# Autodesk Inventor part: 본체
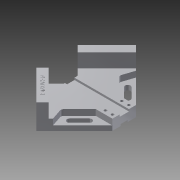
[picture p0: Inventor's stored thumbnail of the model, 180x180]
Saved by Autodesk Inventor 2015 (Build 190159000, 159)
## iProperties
Created: 2019-04
Part Number: 본체
Material: 알루미늄 6061
Document SubType Name: Modeling
Designer: LINEART-SSD.D4.16.04
Density: 2.7 g/cm^3
Appearance: 알루미늄 - 평지
Mass: 608.093 g
Surface Area: 428.235 cm^2
Volume: 225.22 cm^3
Author: LINEART-SSD.D4.16.04
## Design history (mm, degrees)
sketch "스케치1"
  geometry: L1 (-84.853, 0)-(0, -84.853); L2 (0, -84.853)-(84.853, 0); L3 (84.853, 0)-(0, 84.853); L4 (0, 84.853)-(-84.853, 0); L5 (-84.853, 0)-(84.853, 0); L6 (0, -84.853)-(0, 84.853); L7 (-84.853, 0)-(35.147, 0); 1 further point
  constraints: 14 end point, 2 midpoint, 2 parallel, 1 equal length, 1 horizontal, 1 perpendicular
  dimensions: "d0" = 120 distance of L1.start L1.end; "d1" = 45 deg angle of L1 L7; "d2" = 120 distance of L2.end L1.end
extrude "돌출1" new body sketch "스케치1" distance "d3" = 42; taper "d4" = 0 deg
sketch "스케치2"
  geometry: L1 (-84.853, 0)-(0, 84.853); L2 (84.853, 0)-(0, 84.853) reference; L3 (-74.246, -10.607)-(0, 63.64); L4 (0, 63.64)-(74.246, -10.607); L5 (-74.246, -10.607)-(0, -84.853); L6 (-84.853, 0)-(0, -84.853) reference; L7 (0, -84.853)-(74.246, -10.607); 1 further point
  constraints: 10 end point, 3 perpendicular, 1 collinear, 1 other
  dimensions: "d5" = 15 distance between parallel lines of L1 L3
extrude "돌출2" cut sketch "스케치2" distance "d6" = 24; taper "d7" = 0 deg
sketch "스케치3"
  geometry: L1 (0, 84.853)-(-35.355, 49.497); L2 (0, 84.853)-(-84.853, 0) reference; L3 (0, 84.853)-(35.355, 49.497); L4 (84.853, 0)-(0, 84.853) reference; L5 (35.355, 49.497)-(15.47, 29.612); L6 (-11.322, 29.612)-(-33.281, 51.571); L7 (0, -84.853)-(14, -84.853); L8 (0, -64.853)-(14, -64.853); L9 (4.143, 28.147)-(11.934, 28.147); L10 (4.143, 28.147)-(-7.786, 28.147); A1 r 5 centre (-7.786, 33.147) between (-11.322, 29.612) and (-7.786, 28.147); A2 r 5 centre (11.934, 33.147) between (11.934, 28.147) and (15.47, 29.612); 4 further points
  constraints: 16 end point, 9 point on line, 4 point on circle, 4 tangent, 2 centre point, 2 horizontal, 2 parallel, 1 equal radius, 1 perpendicular
  dimensions: "d8" = 50 distance of L1.start L1.end; "d9" = 50 distance of L1.start L3.end; "d12" = 14 distance of L7.start L7.end; "d13" = 20 distance between parallel lines of L7 L8; "d14" = 93 distance between parallel lines of L8 L9; "d16" = 33.12691 distance of point (-9.857, 28.147) L6.end; "d17" = 30.19387 distance of L3.end point (14.005, 28.147); "d18" = 14 distance of L9.start point (-9.857, 28.147); "d19" = 9.85711 distance of L9.start point (14, 28.147); "d20" = 5 radius of A1; "d97" = 14 distance of L8.start L8.end; "d98" = 20 distance of L7.end L8.end
extrude "돌출3" cut sketch "스케치3" stored distance "d21" = 0; taper "d22" = 0 deg
sketch "스케치4"
  geometry: L1 (0, -84.853)-(25, -84.853); L2 (-11, -64.853)-(25, -64.853); L3 (-11, -64.853)-(-25, -64.853); L4 (25, -64.853)-(25, -84.853); L5 (0, -84.853)-(-25, -84.853); L6 (-25, -84.853)-(-25, -64.853); 1 further point
  constraints: 12 end point, 3 horizontal, 1 parallel, 1 perpendicular, 1 vertical
  dimensions: "d23" = 25 distance of L1.start L1.end; "d24" = 20 distance between parallel lines of L1 L2; "d25" = 14 distance of L2.start L3.end; "d28" = 25 distance of L1.start L5.end
extrude "돌출4" cut sketch "스케치4" stored distance "d29" = 24; taper "d30" = 0 deg
sketch "스케치6"
  geometry: L1 (-7.786, 28.147)-(8.214, 28.147); L2 (11.934, 28.147)-(-7.786, 28.147) reference; L3 (-7.786, 28.147)-(-7.786, -64.853); L4 (8.214, 28.147)-(8.214, -64.853); L5 (-7.786, -64.853)-(8.214, -64.853); L6 (-20, -64.853)-(20, -64.853) reference; 1 further point
  constraints: 8 end point, 1 collinear, 1 point on line, 1 vertical
  dimensions: "d39" = 16 distance of L1.start L1.end; "d95" = 93 distance of L4.end L1.end; "d96" = 16 distance of L4.end L3.end
extrude "돌출5" cut sketch "스케치6" distance "d43" = 3.5; taper "d44" = 0 deg
sketch "스케치7"
  geometry: L1 (8.214, 64.853)-(-7.786, 64.853) reference; L2 (-6, -28.147)-(-6, 64.853); L3 (-6, 64.853)-(6, 64.853); L4 (6, 64.853)-(6, -28.147); L5 (6, -28.147)-(-7.343, -28.147); L6 (-7.786, -28.147)-(11.934, -28.147) reference; 2 further points
  constraints: 8 end point, 4 point on line, 1 parallel
  dimensions: "d47" = 12 distance of L2.end L3.end; "d48" = 93 distance of L2.start L2.end; "d49" = 93 distance of L3.end L4.end; "d50" = 13.34265 distance of L4.end L5.end; "d51" = 6 distance from line of L4 point (0, 0)
extrude "돌출6" cut sketch "스케치7" distance "d52" = 3; taper "d53" = 0 deg
sketch "스케치8"
  geometry: L1 (-84.853, 0)-(-70.711, -14.142); L2 (-84.853, 0)-(-20, -64.853) reference; L3 (-20, -64.853)-(-20, -36.569); L4 (-47.312, -9.256)-(-20, -36.569) reference; L5 (-70.711, -14.142)-(-20, -64.853); L6 (-84.853, 0)-(-77.782, 7.071); L7 (-33.281, 51.571)-(-84.853, 0) reference; L8 (-77.782, 7.071)-(-49.497, -21.213); L9 (-77.782, 7.071)-(-37.782, 7.071); L10 (-49.497, -21.213)-(-32.527, -38.184); L11 (-6, -64.853)-(6, -64.853) reference; L12 (0, -64.853)-(0, 0); L13 (20, -64.853)-(20, -36.569); L14 (70.711, -14.142)-(20, -64.853); L15 (-84.853, 0)-(-63.64, -21.213); L16 (-70.711, -14.142)-(-52.429, -8.048); L17 (70.711, -14.142)-(52.429, -8.048); L18 (20, -36.569)-(47.312, -9.256); A1 r 5 centre (-50.848, -12.792) between (-47.312, -9.256) and (-52.429, -8.048); A2 r 5 centre (50.848, -12.792) between (52.429, -8.048) and (47.312, -9.256); 3 further points
  constraints: 32 end point, 8 symmetric about line, 4 point on circle, 3 point on line, 2 centre point, 2 midpoint, 2 tangent, 2 vertical, 1 collinear, 1 equal length, 1 horizontal, 1 parallel, 2 other
  dimensions: "d54" = 20 distance of L1.start L1.end; "d57" = 10 distance of L1.start L6.end; "d58" = 40 distance of L6.end L8.end; "d59" = 45 deg angle of L8 L9; "d60" = 24 distance of L8.end L10.end; "d64" = 30 distance of L1.start L15.end; "d65" = 5 radius of A1; "d66" = 19.27051 distance of L1.end L16.end
extrude "돌출7" cut sketch "스케치8" distance "d62" = 10; taper "d63" = 0 deg
sketch "스케치10"
  geometry: L1 (-84.853, 0)-(-77.782, 7.071); L2 (-33.281, 51.571)-(-84.853, 0) reference; L3 (-84.853, 0)-(-74.853, 0); L4 (-77.782, 7.071)-(-49.497, -21.213); L5 (-77.782, 7.071)-(-37.782, 7.071); L6 (-49.497, -21.213)-(-32.527, -38.184); L7 (-52.679, -24.395)-(-35.709, -41.366); L8 (-29.345, -35.002)-(-46.315, -18.031); L9 (8.214, -64.853)-(-7.786, -64.853) reference; L10 (0.214, -64.853)-(0.214, 28.391); L11 (29.773, -35.002)-(46.743, -18.031); L12 (53.107, -24.395)-(36.137, -41.366); L13 (49.925, -21.213)-(32.955, -38.184); A1 r 4.5 centre (-49.497, -21.213) between (-46.315, -18.031) and (-52.679, -24.395); A2 r 4.5 centre (-32.527, -38.184) between (-35.709, -41.366) and (-29.345, -35.002); A3 r 4.5 centre (49.925, -21.213) between (53.107, -24.395) and (46.743, -18.031); A4 r 4.5 centre (32.955, -38.184) between (29.773, -35.002) and (36.137, -41.366); 3 further points
  constraints: 26 end point, 8 point on circle, 6 symmetric about line, 4 centre point, 4 tangent, 2 equal length, 2 horizontal, 2 midpoint, 1 collinear, 1 parallel, 1 vertical, 2 other
  dimensions: "d67" = 10 distance of L1.start L1.end; "d68" = 45 deg angle of L3 L1 (derived); "d69" = 40 distance of L1.end L4.end; "d70" = 45 deg angle of L4 L5; "d71" = 24 distance of L4.end L6.end; "d72" = 9 diameter of A2; "d73" = 16.97056 horizontal distance of L13.start L13.end
extrude "돌출8" cut sketch "스케치10" stored distance "d74" = 10; taper "d75" = 0 deg
sketch "스케치11"
  geometry: L1 (8.214, -64.853)-(-7.786, -64.853) reference; L2 (0.214, -64.853)-(14.214, -64.853); L3 (20, -64.853)-(6, -64.853) reference; L4 (14.214, -64.853)-(14.214, -58.853); L5 (14.214, -58.853)-(14.214, -46.853); L6 (8, 28.147)-(8, -64.853) reference; L7 (0.214, -64.853)-(0.214, -27.265); C1 r 2.25 at (14.214, -58.853); C2 r 2.25 at (14.214, -46.853); C3 r 2.25 at (-13.786, -46.853); C4 r 2.25 at (-13.786, -58.853); 1 further point
  constraints: 8 end point, 4 centre point, 2 coincident, 2 point on line, 2 symmetric about line, 1 midpoint, 1 perpendicular, 1 vertical, 2 other
  dimensions: "d76" = 14 distance of L2.start L2.end; "d77" = 6 distance of L2.end L4.end; "d78" = 12 distance of L4.end L5.end; "d79" = 4.5 diameter of C1; "d80" = 4.5 diameter of C2; "d84" = 37.58774 distance of L2.start L7.end
extrude "돌출9" cut sketch "스케치11" distance "d82" = 10; taper "d83" = 0 deg
sketch "스케치13"
  geometry: C1 r 2.25 at (0, 0) reference; C2 r 4 at (0, 0); C3 r 2.25 at (0, -12) reference; C4 r 4 at (0, -12); C5 r 2.25 at (28, 0) reference; C6 r 4 at (28, 0); C7 r 2.25 at (28, -12) reference; C8 r 4 at (28, -12); 1 further point
  constraints: 4 centre point, 4 coincident
  dimensions: "d85" = 8 diameter of C2; "d86" = 8 diameter of C4; "d87" = 8 diameter of C6; "d88" = 8 diameter of C8
extrude "돌출10" cut sketch "스케치13" stored distance "d89" = 10; taper "d90" = 0 deg
sketch "스케치14"
  geometry: L1 (-33.281, 51.571)-(-84.853, 0) reference; L2 (-59.067, 25.786)-(-53.764, 20.482); L3 (-59.067, 25.786)-(-51.567, 25.786); 2 further points
  constraints: 4 end point, 1 coincident, 1 equal length, 1 horizontal, 1 midpoint, 1 perpendicular, 1 other
  dimensions: "d91" = 7.5 distance of L2.start L2.end; "d92" = 45 deg angle of L2 L3 (derived)
feature "엠보싱1" sketch "스케치14" dims "d0" = 120, "d1" = 45 deg, "d2" = 120, "d93" = 0.5, "d94" = 0
node "솔리드1"
